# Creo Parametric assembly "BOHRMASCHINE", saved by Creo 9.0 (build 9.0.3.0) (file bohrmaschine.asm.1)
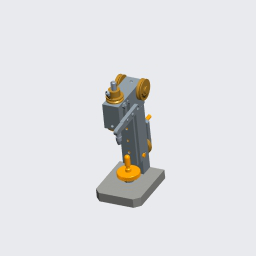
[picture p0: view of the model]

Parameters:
  ERSTELLER = "ARINDA"
  BENENNUNG = "XXX"
  TEILETYP = "K"

Other parameters: MASSE, TRANSLATION1_STATIC_FRICTION, TRANSLATION1_KINETIC_FRICTION, TRANSLATION1_RESTITUTION, TRANSLATION1_MINIMUM_LIMIT, TRANSLATION1_MAXIMUM_LIMIT, TRANSLATION1_ZERO_POSITION, ROTATION1_STATIC_FRICTION, ROTATION1_KINETIC_FRICTION, ROTATION1_CONTACT_RADIUS, ROTATION1_RESTITUTION, ROTATION1_MINIMUM_LIMIT, ROTATION1_MAXIMUM_LIMIT, ROTATION1_ZERO_POSITION

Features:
  1. coordinate system
  2. datum plane "A_RECHTS_Y-Z"
  3. datum plane "A_OBEN_X-Z"
  4. datum plane "A_VORNE_X-Y"
  5. datum axis
  6. datum axis
  7. datum axis
  8. datum point "APNT0"
  9. component "BODENPLATTE"
  10. component "STÄNDER"
  11. component "DIN_912"
  12. component "BOHRMASCHINENKOPF"
  13. component "ISO7434_M4X4"
  14. component "FÜHRUNGSLEISTE"
  15. component "DIN913_45H"
  16. component "ISO4032_1"
  17. pattern
  18. component "ISO2338"
  19. component "ISO2338"
  20. component "DIN_912"
  21. component "RÄNDELSCHRAUBE"
  22. component "MASCHINENTISCH"
  23. component "ANTRIEBSSCHEIBE"
  24. component "ISO7435"
  25. component "ISO4032_1"
  26. component "ISO7090T1"
  27. component "KURBEL"
  28. component "ISO4032_1"
  29. component "ISO2338"
  30. component
  31. component
  32. component
  33. component
  34. component
  35. component "HEBEL"

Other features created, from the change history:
  planar section "XSEC0001" (2 times)
  planar section "XSEC0002"
  feature "Motor 1"
  component "DIN7513M3BX6.PRT"
  component "RIEMEN.PRT"
  group "COPIED_GROUP"

Other named items: AA_X, AA_Y, AA_Z, ACS0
